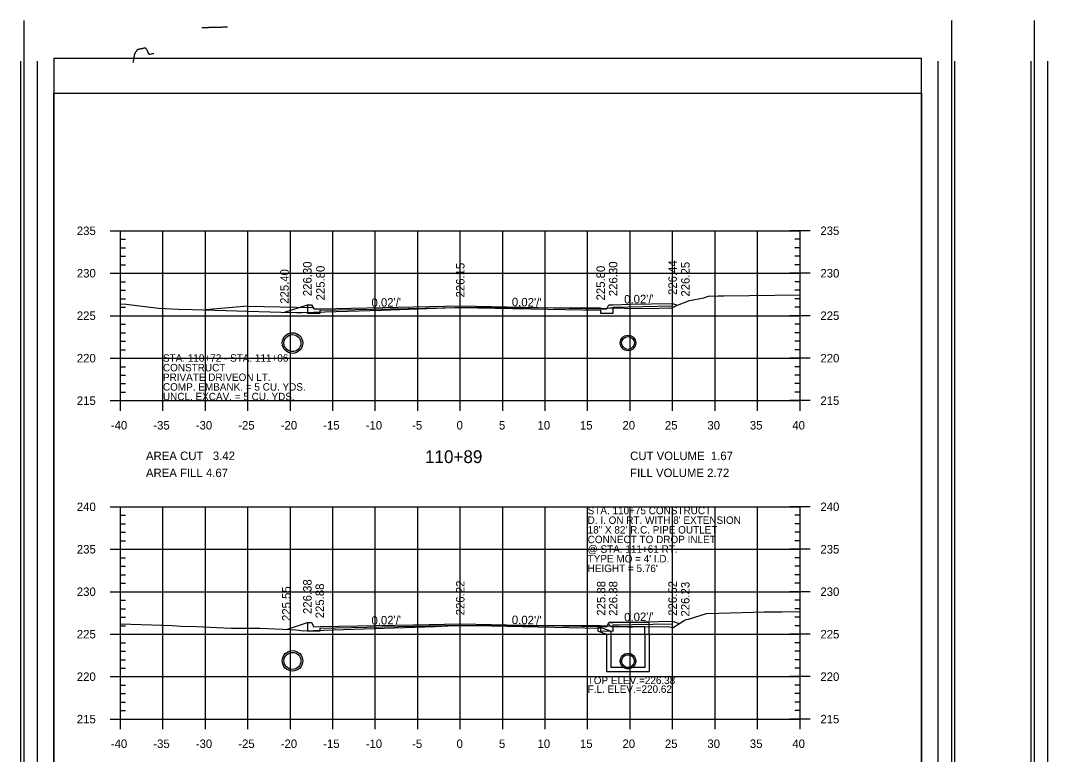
# Model space of a CAD drawing. Extents: x 1367903 to 1373764, y 376865 to 382130.
# Drawn here: x 1372354.5 to 1372596.3, y 377447.5 to 377620.4 of the extents above; entities that cross this region are included whole.
import ezdxf

# ---------------------------------------------------------------- set-up
doc = ezdxf.new("R2010")
doc.units = 0
for name, color, linetype in [('R_Axis', 7, 'Continuous'), ('R_Axis Annot', 7, 'Continuous'), ('R_Border', 7, 'Continuous'), ('R_Border PE', 7, 'Continuous'), ('R_Draft', 7, 'Continuous'), ('R_Drive', 7, 'Continuous'), ('R_Exist Surface', 7, 'Continuous'), ('R_Fin Surface', 7, 'Continuous'), ('R_Fin Surface Annot', 7, 'Continuous'), ('R_Grid', 7, 'Continuous'), ('R_Water', 7, 'Continuous'), ('R_Water Annot', 7, 'Continuous')]:
    doc.layers.add(name, color=color, linetype=linetype)

msp = doc.modelspace()

# ---------------------------------------------------------------- linework, layer by layer
for p, q in [((1372490.54, 377477.63), (1372493.54, 377476.59)), ((1372492.88, 377478.26), (1372493.04, 377478.59)), ((1372492.88, 377478.26), (1372493.54, 377477.59)), ((1372502.54, 377478.59), (1372493.04, 377478.59)), ((1372501.54, 377477.59), (1372493.54, 377477.59)), ((1372501.54, 377475.59), (1372501.54, 377477.59)), ((1372502.54, 377475.59), (1372502.54, 377478.59)), ((1372490.54, 377476.57), (1372492.54, 377475.88)), ((1372492.54, 377475.59), (1372492.54, 377475.88)), ((1372493.54, 377475.59), (1372493.54, 377476.59))]:
    msp.add_line(p, q)
for points in [[(1372422.04, 377553.44), (1372422.04, 377552.77), (1372422.04, 377552.77), (1372422.04, 377551.41), (1372425.04, 377551.47), (1372425.04, 377552.13), (1372458.04, 377552.79), (1372491.04, 377552.13), (1372491.04, 377551.47), (1372494.04, 377551.41), (1372494.04, 377552.85), (1372508.04, 377553.13), (1372508.04, 377553.72)], [(1372422.04, 377478.59), (1372422.04, 377477.93), (1372422.04, 377477.93), (1372422.04, 377476.56), (1372425.04, 377476.62), (1372425.04, 377477.29), (1372458.04, 377477.95), (1372491.04, 377477.29), (1372491.04, 377476.62), (1372494.04, 377476.56), (1372494.04, 377478.01), (1372508.04, 377478.29), (1372508.04, 377478.87)], [(1372490.54, 377476.57), (1372490.54, 377477.63)]]:
    msp.add_lwpolyline(points)
at = {"layer": 'R_Axis'}
for p, q in [((1372375.64, 377570.84), (1372380.44, 377570.84)), ((1372378.04, 377530.84), (1372378.04, 377570.84)), ((1372540.44, 377570.84), (1372535.64, 377570.84)), ((1372538.04, 377530.84), (1372538.04, 377570.84)), ((1372378.04, 377568.84), (1372379.24, 377568.84)), ((1372378.04, 377566.84), (1372379.24, 377566.84)), ((1372538.04, 377568.84), (1372536.84, 377568.84)), ((1372538.04, 377566.84), (1372536.84, 377566.84)), ((1372378.04, 377564.84), (1372379.24, 377564.84)), ((1372538.04, 377564.84), (1372536.84, 377564.84)), ((1372378.04, 377562.84), (1372379.24, 377562.84)), ((1372538.04, 377562.84), (1372536.84, 377562.84)), ((1372375.64, 377560.84), (1372380.44, 377560.84)), ((1372540.44, 377560.84), (1372535.64, 377560.84)), ((1372378.04, 377558.84), (1372379.24, 377558.84)), ((1372538.04, 377558.84), (1372536.84, 377558.84)), ((1372378.04, 377556.84), (1372379.24, 377556.84)), ((1372378.04, 377554.84), (1372379.24, 377554.84)), ((1372538.04, 377556.84), (1372536.84, 377556.84)), ((1372538.04, 377554.84), (1372536.84, 377554.84)), ((1372378.04, 377552.84), (1372379.24, 377552.84)), ((1372538.04, 377552.84), (1372536.84, 377552.84)), ((1372375.64, 377550.84), (1372380.44, 377550.84)), ((1372540.44, 377550.84), (1372535.64, 377550.84)), ((1372378.04, 377548.84), (1372379.24, 377548.84)), ((1372538.04, 377548.84), (1372536.84, 377548.84)), ((1372378.04, 377546.84), (1372379.24, 377546.84)), ((1372538.04, 377546.84), (1372536.84, 377546.84)), ((1372378.04, 377544.84), (1372379.24, 377544.84)), ((1372378.04, 377542.84), (1372379.24, 377542.84)), ((1372538.04, 377544.84), (1372536.84, 377544.84)), ((1372538.04, 377542.84), (1372536.84, 377542.84)), ((1372375.64, 377540.84), (1372380.44, 377540.84)), ((1372540.44, 377540.84), (1372535.64, 377540.84)), ((1372378.04, 377538.84), (1372379.24, 377538.84)), ((1372538.04, 377538.84), (1372536.84, 377538.84)), ((1372378.04, 377536.84), (1372379.24, 377536.84)), ((1372538.04, 377536.84), (1372536.84, 377536.84)), ((1372378.04, 377534.84), (1372379.24, 377534.84)), ((1372378.04, 377528.44), (1372378.04, 377533.24)), ((1372388.04, 377528.44), (1372388.04, 377533.24)), ((1372398.04, 377528.44), (1372398.04, 377533.24)), ((1372408.04, 377528.44), (1372408.04, 377533.24)), ((1372418.04, 377528.44), (1372418.04, 377533.24)), ((1372428.04, 377528.44), (1372428.04, 377533.24)), ((1372438.04, 377528.44), (1372438.04, 377533.24)), ((1372448.04, 377528.44), (1372448.04, 377533.24)), ((1372458.04, 377528.44), (1372458.04, 377533.24)), ((1372468.04, 377528.44), (1372468.04, 377533.24)), ((1372478.04, 377528.44), (1372478.04, 377533.24)), ((1372488.04, 377528.44), (1372488.04, 377533.24)), ((1372498.04, 377528.44), (1372498.04, 377533.24)), ((1372508.04, 377528.44), (1372508.04, 377533.24)), ((1372518.04, 377528.44), (1372518.04, 377533.24)), ((1372528.04, 377528.44), (1372528.04, 377533.24)), ((1372538.04, 377534.84), (1372536.84, 377534.84)), ((1372538.04, 377528.44), (1372538.04, 377533.24)), ((1372375.64, 377530.84), (1372380.44, 377530.84)), ((1372378.04, 377532.84), (1372379.24, 377532.84)), ((1372378.04, 377530.84), (1372538.04, 377530.84)), ((1372540.44, 377530.84), (1372535.64, 377530.84)), ((1372538.04, 377532.84), (1372536.84, 377532.84)), ((1372375.64, 377505.84), (1372380.44, 377505.84)), ((1372378.04, 377455.84), (1372378.04, 377505.84)), ((1372540.44, 377505.84), (1372535.64, 377505.84)), ((1372538.04, 377455.84), (1372538.04, 377505.84)), ((1372378.04, 377503.84), (1372379.24, 377503.84)), ((1372378.04, 377501.84), (1372379.24, 377501.84)), ((1372538.04, 377503.84), (1372536.84, 377503.84)), ((1372538.04, 377501.84), (1372536.84, 377501.84)), ((1372378.04, 377499.84), (1372379.24, 377499.84)), ((1372538.04, 377499.84), (1372536.84, 377499.84)), ((1372378.04, 377497.84), (1372379.24, 377497.84)), ((1372538.04, 377497.84), (1372536.84, 377497.84)), ((1372375.64, 377495.84), (1372380.44, 377495.84)), ((1372540.44, 377495.84), (1372535.64, 377495.84)), ((1372378.04, 377493.84), (1372379.24, 377493.84)), ((1372538.04, 377493.84), (1372536.84, 377493.84)), ((1372378.04, 377491.84), (1372379.24, 377491.84)), ((1372378.04, 377489.84), (1372379.24, 377489.84)), ((1372538.04, 377491.84), (1372536.84, 377491.84)), ((1372538.04, 377489.84), (1372536.84, 377489.84)), ((1372378.04, 377487.84), (1372379.24, 377487.84)), ((1372538.04, 377487.84), (1372536.84, 377487.84)), ((1372375.64, 377485.84), (1372380.44, 377485.84)), ((1372540.44, 377485.84), (1372535.64, 377485.84)), ((1372378.04, 377483.84), (1372379.24, 377483.84)), ((1372538.04, 377483.84), (1372536.84, 377483.84)), ((1372378.04, 377481.84), (1372379.24, 377481.84)), ((1372378.04, 377479.84), (1372379.24, 377479.84)), ((1372538.04, 377481.84), (1372536.84, 377481.84)), ((1372538.04, 377479.84), (1372536.84, 377479.84)), ((1372378.04, 377477.84), (1372379.24, 377477.84)), ((1372538.04, 377477.84), (1372536.84, 377477.84)), ((1372375.64, 377475.84), (1372380.44, 377475.84)), ((1372540.44, 377475.84), (1372535.64, 377475.84)), ((1372378.04, 377473.84), (1372379.24, 377473.84)), ((1372538.04, 377473.84), (1372536.84, 377473.84)), ((1372378.04, 377471.84), (1372379.24, 377471.84)), ((1372538.04, 377471.84), (1372536.84, 377471.84)), ((1372378.04, 377469.84), (1372379.24, 377469.84)), ((1372378.04, 377467.84), (1372379.24, 377467.84)), ((1372538.04, 377469.84), (1372536.84, 377469.84)), ((1372538.04, 377467.84), (1372536.84, 377467.84)), ((1372375.64, 377465.84), (1372380.44, 377465.84)), ((1372540.44, 377465.84), (1372535.64, 377465.84)), ((1372378.04, 377463.84), (1372379.24, 377463.84)), ((1372538.04, 377463.84), (1372536.84, 377463.84)), ((1372378.04, 377461.84), (1372379.24, 377461.84)), ((1372538.04, 377461.84), (1372536.84, 377461.84)), ((1372378.04, 377459.84), (1372379.24, 377459.84)), ((1372378.04, 377453.44), (1372378.04, 377458.24)), ((1372388.04, 377453.44), (1372388.04, 377458.24)), ((1372398.04, 377453.44), (1372398.04, 377458.24)), ((1372408.04, 377453.44), (1372408.04, 377458.24)), ((1372418.04, 377453.44), (1372418.04, 377458.24)), ((1372428.04, 377453.44), (1372428.04, 377458.24)), ((1372438.04, 377453.44), (1372438.04, 377458.24)), ((1372448.04, 377453.44), (1372448.04, 377458.24)), ((1372458.04, 377453.44), (1372458.04, 377458.24)), ((1372468.04, 377453.44), (1372468.04, 377458.24)), ((1372478.04, 377453.44), (1372478.04, 377458.24)), ((1372488.04, 377453.44), (1372488.04, 377458.24)), ((1372498.04, 377453.44), (1372498.04, 377458.24)), ((1372508.04, 377453.44), (1372508.04, 377458.24)), ((1372518.04, 377453.44), (1372518.04, 377458.24)), ((1372528.04, 377453.44), (1372528.04, 377458.24)), ((1372538.04, 377459.84), (1372536.84, 377459.84)), ((1372538.04, 377453.44), (1372538.04, 377458.24)), ((1372375.64, 377455.84), (1372380.44, 377455.84)), ((1372378.04, 377457.84), (1372379.24, 377457.84)), ((1372378.04, 377455.84), (1372538.04, 377455.84)), ((1372540.44, 377455.84), (1372535.64, 377455.84)), ((1372538.04, 377457.84), (1372536.84, 377457.84))]:
    msp.add_line(p, q, dxfattribs=at)
at = {"layer": 'R_Border'}
for p, q in [((1372355.31, 377620.35), (1372355.31, 377279.12)), ((1372573.71, 377620.35), (1372573.71, 377279.12)), ((1372593.2, 377620.35), (1372593.2, 377279.12)), ((1372362.34, 377611.47), (1372566.67, 377611.47)), ((1372362.34, 377611.47), (1372362.34, 377280.59)), ((1372566.67, 377280.59), (1372566.67, 377611.47))]:
    msp.add_line(p, q, dxfattribs=at)
at = {"layer": 'R_Border PE'}
for p, q in [((1372354.51, 377610.76), (1372354.51, 377288.8)), ((1372358.42, 377610.76), (1372358.42, 377288.8)), ((1372570.59, 377288.8), (1372570.59, 377610.76)), ((1372574.51, 377288.8), (1372574.51, 377610.76)), ((1372592.39, 377610.76), (1372592.39, 377288.8)), ((1372596.31, 377610.76), (1372596.31, 377288.8)), ((1372362.34, 377603.25), (1372566.67, 377603.25)), ((1372362.34, 377288.8), (1372362.34, 377603.25)), ((1372566.67, 377603.25), (1372566.67, 377288.8))]:
    msp.add_line(p, q, dxfattribs=at)
for points in [[(1372399.2, 377618.69), (1372399.15, 377618.69), (1372398.87, 377618.68), (1372398.74, 377618.68), (1372398.67, 377618.67), (1372398.51, 377618.67), (1372398.16, 377618.66), (1372397.83, 377618.65), (1372397.19, 377618.63)], [(1372399.65, 377618.7), (1372399.2, 377618.69)], [(1372403.22, 377618.79), (1372402.87, 377618.78), (1372402.67, 377618.78), (1372402.51, 377618.77), (1372402.28, 377618.76), (1372402.12, 377618.76), (1372401.93, 377618.75), (1372401.68, 377618.75), (1372401.49, 377618.74), (1372401.21, 377618.73), (1372401.11, 377618.73), (1372401.06, 377618.73), (1372400.84, 377618.72), (1372400.73, 377618.72), (1372400.51, 377618.71), (1372400.43, 377618.72), (1372400.01, 377618.7), (1372399.77, 377618.7), (1372399.65, 377618.7)], [(1372385.9, 377612.54), (1372385.88, 377612.55), (1372385.86, 377612.55), (1372385.84, 377612.55), (1372385.82, 377612.55), (1372385.79, 377612.55), (1372385.76, 377612.55), (1372385.74, 377612.55), (1372385.6, 377612.51), (1372385.48, 377612.48), (1372385.21, 377612.41), (1372385, 377612.36), (1372384.97, 377612.35), (1372384.95, 377612.35), (1372384.93, 377612.34), (1372384.92, 377612.34), (1372384.91, 377612.35), (1372384.88, 377612.35), (1372384.86, 377612.36), (1372384.83, 377612.38), (1372384.82, 377612.39), (1372384.8, 377612.4), (1372384.78, 377612.42), (1372384.76, 377612.45), (1372384.75, 377612.47), (1372384.73, 377612.5), (1372384.71, 377612.55), (1372384.62, 377612.76), (1372384.51, 377613), (1372384.4, 377613.23), (1372384.39, 377613.26), (1372384.38, 377613.28), (1372384.34, 377613.34), (1372384.31, 377613.39), (1372384.19, 377613.57), (1372384.11, 377613.69), (1372384.08, 377613.74), (1372384.06, 377613.76), (1372384.05, 377613.78), (1372384.02, 377613.81), (1372384.01, 377613.83), (1372383.99, 377613.84), (1372383.98, 377613.85), (1372383.95, 377613.87), (1372383.94, 377613.87), (1372383.91, 377613.88), (1372383.88, 377613.88), (1372383.87, 377613.88), (1372383.83, 377613.88), (1372383.73, 377613.86), (1372383.56, 377613.82), (1372383.36, 377613.77), (1372383.22, 377613.74), (1372383.11, 377613.72), (1372382.97, 377613.69), (1372382.85, 377613.66), (1372382.67, 377613.63), (1372382.45, 377613.58), (1372382.41, 377613.57), (1372382.28, 377613.54), (1372382.17, 377613.52), (1372382.13, 377613.51), (1372382.1, 377613.5), (1372382.08, 377613.5), (1372382.06, 377613.49), (1372382.05, 377613.49), (1372382.03, 377613.47), (1372382.01, 377613.46), (1372381.99, 377613.44), (1372381.96, 377613.42), (1372381.93, 377613.39), (1372381.91, 377613.35), (1372381.88, 377613.31), (1372381.84, 377613.26), (1372381.78, 377613.16), (1372381.69, 377613.02), (1372381.6, 377612.89), (1372381.51, 377612.75), (1372381.46, 377612.67), (1372381.42, 377612.62), (1372381.38, 377612.55), (1372381.37, 377612.54), (1372381.36, 377612.52), (1372381.36, 377612.5), (1372381.35, 377612.48), (1372381.34, 377612.46), (1372381.34, 377612.44), (1372381.33, 377612.42), (1372381.32, 377612.39), (1372381.32, 377612.37), (1372381.31, 377612.35), (1372381.31, 377612.33), (1372381.29, 377612.24), (1372381.25, 377612), (1372381.21, 377611.76), (1372381.19, 377611.65), (1372381.1, 377611.18), (1372381.08, 377611.04), (1372381.04, 377610.84), (1372380.99, 377610.54), (1372380.96, 377610.39)]]:
    msp.add_lwpolyline(points, dxfattribs=at)
at = {"layer": 'R_Drive'}
for q in [(1372398.04, 377552.2), (1372423.37, 377552.78)]:
    msp.add_line((1372408.04, 377553.09), q, dxfattribs=at)
at = {"layer": 'R_Exist Surface'}
for points in [[(1372378.04, 377553.61), (1372379.34, 377553.53), (1372386.99, 377552.6), (1372391.64, 377552.38), (1372394.97, 377552.29), (1372415.84, 377551.66), (1372419.47, 377551.58), (1372420.8, 377551.56), (1372439.5, 377552.15), (1372456.75, 377552.76), (1372474.44, 377552.78), (1372490.95, 377552.68), (1372491.62, 377552.56), (1372493.29, 377552.7), (1372494.77, 377552.66), (1372496.63, 377552.6), (1372497.54, 377552.52), (1372504.99, 377552.65), (1372507.2, 377552.67), (1372507.48, 377552.59), (1372508.11, 377552.74), (1372508.79, 377553.19), (1372512.04, 377554.4), (1372515.37, 377555.07), (1372516.53, 377555.43), (1372518.8, 377555.5), (1372520.18, 377555.53), (1372538.04, 377555.73)], [(1372378.04, 377478.29), (1372390.18, 377477.85), (1372392.36, 377477.76), (1372395.97, 377477.67), (1372400.71, 377477.43), (1372404.1, 377477.28), (1372410.92, 377477.24), (1372417.95, 377476.91), (1372419.34, 377476.85), (1372421.14, 377476.6), (1372452.09, 377477.69), (1372456.8, 377477.86), (1372459.91, 377477.86), (1372491.06, 377477.86), (1372492.38, 377477.84), (1372495.39, 377477.76), (1372496.65, 377477.65), (1372497.49, 377477.58), (1372498.7, 377477.6), (1372506.99, 377477.68), (1372508.06, 377477.39), (1372508.17, 377477.42), (1372510.74, 377479.09), (1372511.24, 377479.28), (1372511.75, 377479.38), (1372516.06, 377480.7), (1372524.46, 377480.96), (1372529.57, 377481.07), (1372533.74, 377481.11), (1372538.04, 377481.22)]]:
    msp.add_lwpolyline(points, dxfattribs=at)
at = {"layer": 'R_Fin Surface'}
for points in [[(1372416.66, 377551.64), (1372422.04, 377553.44), (1372423.04, 377553.44), (1372423.54, 377552.44), (1372425.04, 377552.47), (1372447.04, 377552.91), (1372458.04, 377553.13), (1372469.04, 377552.91), (1372491.04, 377552.47), (1372492.54, 377552.44), (1372493.04, 377553.44), (1372494.04, 377553.44), (1372498.04, 377553.52), (1372508.04, 377553.72), (1372509.19, 377553.34)], [(1372417.11, 377476.95), (1372422.04, 377478.59), (1372423.04, 377478.59), (1372423.54, 377477.59), (1372425.04, 377477.62), (1372447.04, 377478.06), (1372458.04, 377478.28), (1372469.04, 377478.06), (1372491.04, 377477.62), (1372492.54, 377477.59), (1372493.04, 377478.59), (1372494.04, 377478.59), (1372498.04, 377478.67), (1372508.04, 377478.87), (1372509.6, 377478.35)]]:
    msp.add_lwpolyline(points, dxfattribs=at)
at = {"layer": 'R_Grid'}
for p, q in [((1372378.04, 377570.84), (1372538.04, 377570.84)), ((1372378.04, 377530.84), (1372378.04, 377570.84)), ((1372388.04, 377530.84), (1372388.04, 377570.84)), ((1372398.04, 377530.84), (1372398.04, 377570.84)), ((1372408.04, 377530.84), (1372408.04, 377570.84)), ((1372418.04, 377530.84), (1372418.04, 377570.84)), ((1372428.04, 377530.84), (1372428.04, 377570.84)), ((1372438.04, 377530.84), (1372438.04, 377570.84)), ((1372448.04, 377530.84), (1372448.04, 377570.84)), ((1372458.04, 377530.84), (1372458.04, 377570.84)), ((1372468.04, 377530.84), (1372468.04, 377570.84)), ((1372478.04, 377530.84), (1372478.04, 377570.84)), ((1372488.04, 377530.84), (1372488.04, 377570.84)), ((1372498.04, 377530.84), (1372498.04, 377570.84)), ((1372508.04, 377530.84), (1372508.04, 377570.84)), ((1372518.04, 377530.84), (1372518.04, 377570.84)), ((1372528.04, 377530.84), (1372528.04, 377570.84)), ((1372538.04, 377530.84), (1372538.04, 377570.84)), ((1372378.04, 377560.84), (1372538.04, 377560.84)), ((1372378.04, 377550.84), (1372538.04, 377550.84)), ((1372378.04, 377540.84), (1372538.04, 377540.84)), ((1372378.04, 377530.84), (1372538.04, 377530.84)), ((1372378.04, 377505.84), (1372538.04, 377505.84)), ((1372378.04, 377455.84), (1372378.04, 377505.84)), ((1372388.04, 377455.84), (1372388.04, 377505.84)), ((1372398.04, 377455.84), (1372398.04, 377505.84)), ((1372408.04, 377455.84), (1372408.04, 377505.84)), ((1372418.04, 377455.84), (1372418.04, 377505.84)), ((1372428.04, 377455.84), (1372428.04, 377505.84)), ((1372438.04, 377455.84), (1372438.04, 377505.84)), ((1372448.04, 377455.84), (1372448.04, 377505.84)), ((1372458.04, 377455.84), (1372458.04, 377505.84)), ((1372468.04, 377455.84), (1372468.04, 377505.84)), ((1372478.04, 377455.84), (1372478.04, 377505.84)), ((1372488.04, 377455.84), (1372488.04, 377505.84)), ((1372498.04, 377455.84), (1372498.04, 377505.84)), ((1372508.04, 377455.84), (1372508.04, 377505.84)), ((1372518.04, 377455.84), (1372518.04, 377505.84)), ((1372528.04, 377455.84), (1372528.04, 377505.84)), ((1372538.04, 377455.84), (1372538.04, 377505.84)), ((1372378.04, 377495.84), (1372538.04, 377495.84)), ((1372378.04, 377485.84), (1372538.04, 377485.84)), ((1372378.04, 377475.84), (1372538.04, 377475.84)), ((1372378.04, 377465.84), (1372538.04, 377465.84)), ((1372378.04, 377455.84), (1372538.04, 377455.84))]:
    msp.add_line(p, q, dxfattribs=at)
at = {"layer": 'R_Water'}
for p, q in [((1372418.54, 377546.84), (1372418.54, 377546.79)), ((1372418.54, 377546.42), (1372418.54, 377546.37)), ((1372497.54, 377546.27), (1372497.54, 377546.22)), ((1372497.54, 377545.93), (1372497.54, 377545.89)), ((1372497.54, 377542.93), (1372497.54, 377542.89)), ((1372418.54, 377542.42), (1372418.54, 377542.37)), ((1372418.54, 377542), (1372418.54, 377541.95)), ((1372497.54, 377542.6), (1372497.54, 377542.55)), ((1372418.54, 377472), (1372418.54, 377471.96)), ((1372418.54, 377471.59), (1372418.54, 377471.54)), ((1372418.54, 377467.59), (1372418.54, 377467.54)), ((1372418.54, 377467.17), (1372418.54, 377467.12))]:
    msp.add_line(p, q, dxfattribs=at)
for points in [[(1372502.54, 377475.59), (1372502.54, 377466.99), (1372497.54, 377466.99), (1372492.54, 377466.99), (1372492.54, 377475.59)], [(1372501.54, 377475.59), (1372501.54, 377467.99), (1372497.54, 377467.99), (1372493.54, 377467.99), (1372493.54, 377475.59)]]:
    msp.add_lwpolyline(points, dxfattribs=at)
for centre, radius in [((1372418.54, 377544.4), 2.42), ((1372418.54, 377544.4), 2), ((1372497.54, 377544.41), 1.83), ((1372497.54, 377544.41), 1.5), ((1372418.54, 377469.56), 2.42), ((1372418.54, 377469.56), 2), ((1372497.54, 377469.49), 1.83), ((1372497.54, 377469.49), 1.5)]:
    msp.add_circle(centre, radius, dxfattribs=at)

# ---------------------------------------------------------------- texts
at = {"layer": 'R_Axis Annot'}
for s, height, p in [('235', 2, (1372367.76, 377569.84)), ('235', 2, (1372542.84, 377569.84)), ('230', 2, (1372367.76, 377559.84)), ('230', 2, (1372542.84, 377559.84)), ('225', 2, (1372367.76, 377549.84)), ('225', 2, (1372542.84, 377549.84)), ('220', 2, (1372367.76, 377539.84)), ('220', 2, (1372542.84, 377539.84)), ('215', 2, (1372367.76, 377529.84)), ('215', 2, (1372542.84, 377529.84)), ('-40', 2, (1372375.77, 377524.04)), ('-35', 2, (1372385.77, 377524.04)), ('-30', 2, (1372395.77, 377524.04)), ('-25', 2, (1372405.77, 377524.04)), ('-20', 2, (1372415.77, 377524.04)), ('-15', 2, (1372425.77, 377524.04)), ('-10', 2, (1372435.77, 377524.04)), ('-5', 2, (1372446.7, 377524.04)), ('0', 2, (1372457.17, 377524.04)), ('5', 2, (1372467.16, 377524.04)), ('10', 2, (1372476.23, 377524.04)), ('15', 2, (1372486.23, 377524.04)), ('20', 2, (1372496.23, 377524.04)), ('25', 2, (1372506.23, 377524.04)), ('30', 2, (1372516.23, 377524.04)), ('35', 2, (1372526.23, 377524.04)), ('40', 2, (1372536.23, 377524.04)), ('AREA CUT   3.42', 2, (1372384.04, 377516.84)), ('110+89', 3, (1372449.75, 377516.14)), ('CUT VOLUME  1.67', 2, (1372498.04, 377516.84)), ('AREA FILL 4.67', 2, (1372384.04, 377512.84)), ('FILL VOLUME 2.72', 2, (1372498.04, 377512.84)), ('240', 2, (1372367.76, 377504.84)), ('240', 2, (1372542.84, 377504.84)), ('235', 2, (1372367.76, 377494.84)), ('235', 2, (1372542.84, 377494.84)), ('230', 2, (1372367.76, 377484.84)), ('230', 2, (1372542.84, 377484.84)), ('225', 2, (1372367.76, 377474.84)), ('225', 2, (1372542.84, 377474.84)), ('220', 2, (1372367.76, 377464.84)), ('220', 2, (1372542.84, 377464.84)), ('215', 2, (1372367.76, 377454.84)), ('215', 2, (1372542.84, 377454.84)), ('-40', 2, (1372375.77, 377449.04)), ('-35', 2, (1372385.77, 377449.04)), ('-30', 2, (1372395.77, 377449.04)), ('-25', 2, (1372405.77, 377449.04)), ('-20', 2, (1372415.77, 377449.04)), ('-15', 2, (1372425.77, 377449.04)), ('-10', 2, (1372435.77, 377449.04)), ('-5', 2, (1372446.7, 377449.04)), ('0', 2, (1372457.17, 377449.04)), ('5', 2, (1372467.16, 377449.04)), ('10', 2, (1372476.23, 377449.04)), ('15', 2, (1372486.23, 377449.04)), ('20', 2, (1372496.23, 377449.04)), ('25', 2, (1372506.23, 377449.04)), ('30', 2, (1372516.23, 377449.04)), ('35', 2, (1372526.23, 377449.04)), ('40', 2, (1372536.23, 377449.04))]:
    msp.add_text(s, height=height, dxfattribs=at).set_placement(p)
at = {"layer": 'R_Draft'}
for s, p in [('STA. 110+72 - STA. 111+06', (1372388.04, 377540.01)), ('CONSTRUCT', (1372388.04, 377537.74)), ('PRIVATE DRIVEON LT.', (1372388.04, 377535.47)), ('COMP. EMBANK. = 5 CU. YDS.', (1372388.04, 377533.2)), ('UNCL. EXCAV. = 5 CU. YDS.', (1372388.04, 377530.93)), ('STA. 110+75 CONSTRUCT', (1372488.04, 377504.09)), ("D. I. ON RT. WITH 8' EXTENSION", (1372488.04, 377501.82)), ('18" X 82\' R.C. PIPE OUTLET', (1372488.04, 377499.55)), ('CONNECT TO DROP INLET', (1372488.04, 377497.28)), ('@ STA. 111+61 RT.', (1372488.04, 377495.01)), ("TYPE MO = 4' I.D.", (1372488.04, 377492.74)), ("HEIGHT = 5.76'", (1372488.04, 377490.47))]:
    msp.add_text(s, height=1.75, dxfattribs=at).set_placement(p)
at = {"layer": 'R_Fin Surface Annot'}
for s, rotation, p in [('226.30', 90, (1372423.04, 377555.44)), ('225.80', 90, (1372426.13, 377554.44)), ('226.15', 90, (1372459.04, 377555.13)), ('225.80', 90, (1372492.11, 377554.44)), ('226.30', 90, (1372495.04, 377555.44)), ('226.44', 90, (1372509.04, 377555.72)), ('226.25', 90, (1372512.05, 377555.34)), ('225.40', 90, (1372417.66, 377553.64)), ("0.02'/'", 1.1458, (1372437.16, 377552.91)), ("0.02'/'", 358.8542, (1372470.17, 377553.09)), ("0.02'/'", 1.1458, (1372496.66, 377553.69)), ('226.38', 90, (1372423.04, 377480.59)), ('225.88', 90, (1372425.97, 377479.59)), ('226.22', 90, (1372459.04, 377480.28)), ('225.88', 90, (1372492.22, 377480.18)), ('226.38', 90, (1372495.04, 377480.16)), ('226.52', 90, (1372509.04, 377480.18)), ('226.23', 90, (1372512.02, 377479.99)), ('225.55', 90, (1372418.09, 377478.94)), ("0.02'/'", 1.1458, (1372437.16, 377478.07)), ("0.02'/'", 358.8542, (1372470.17, 377478.24)), ("0.02'/'", 1.1458, (1372496.66, 377478.85))]:
    msp.add_text(s, height=2, rotation=rotation, dxfattribs=at).set_placement(p)
at = {"layer": 'R_Water Annot'}
for s, p in [('TOP ELEV.=226.38', (1372488.04, 377464.09)), ('F.L. ELEV.=220.62', (1372488.04, 377462.03))]:
    msp.add_text(s, height=1.75, dxfattribs=at).set_placement(p)

doc.saveas('drawing.dxf')
